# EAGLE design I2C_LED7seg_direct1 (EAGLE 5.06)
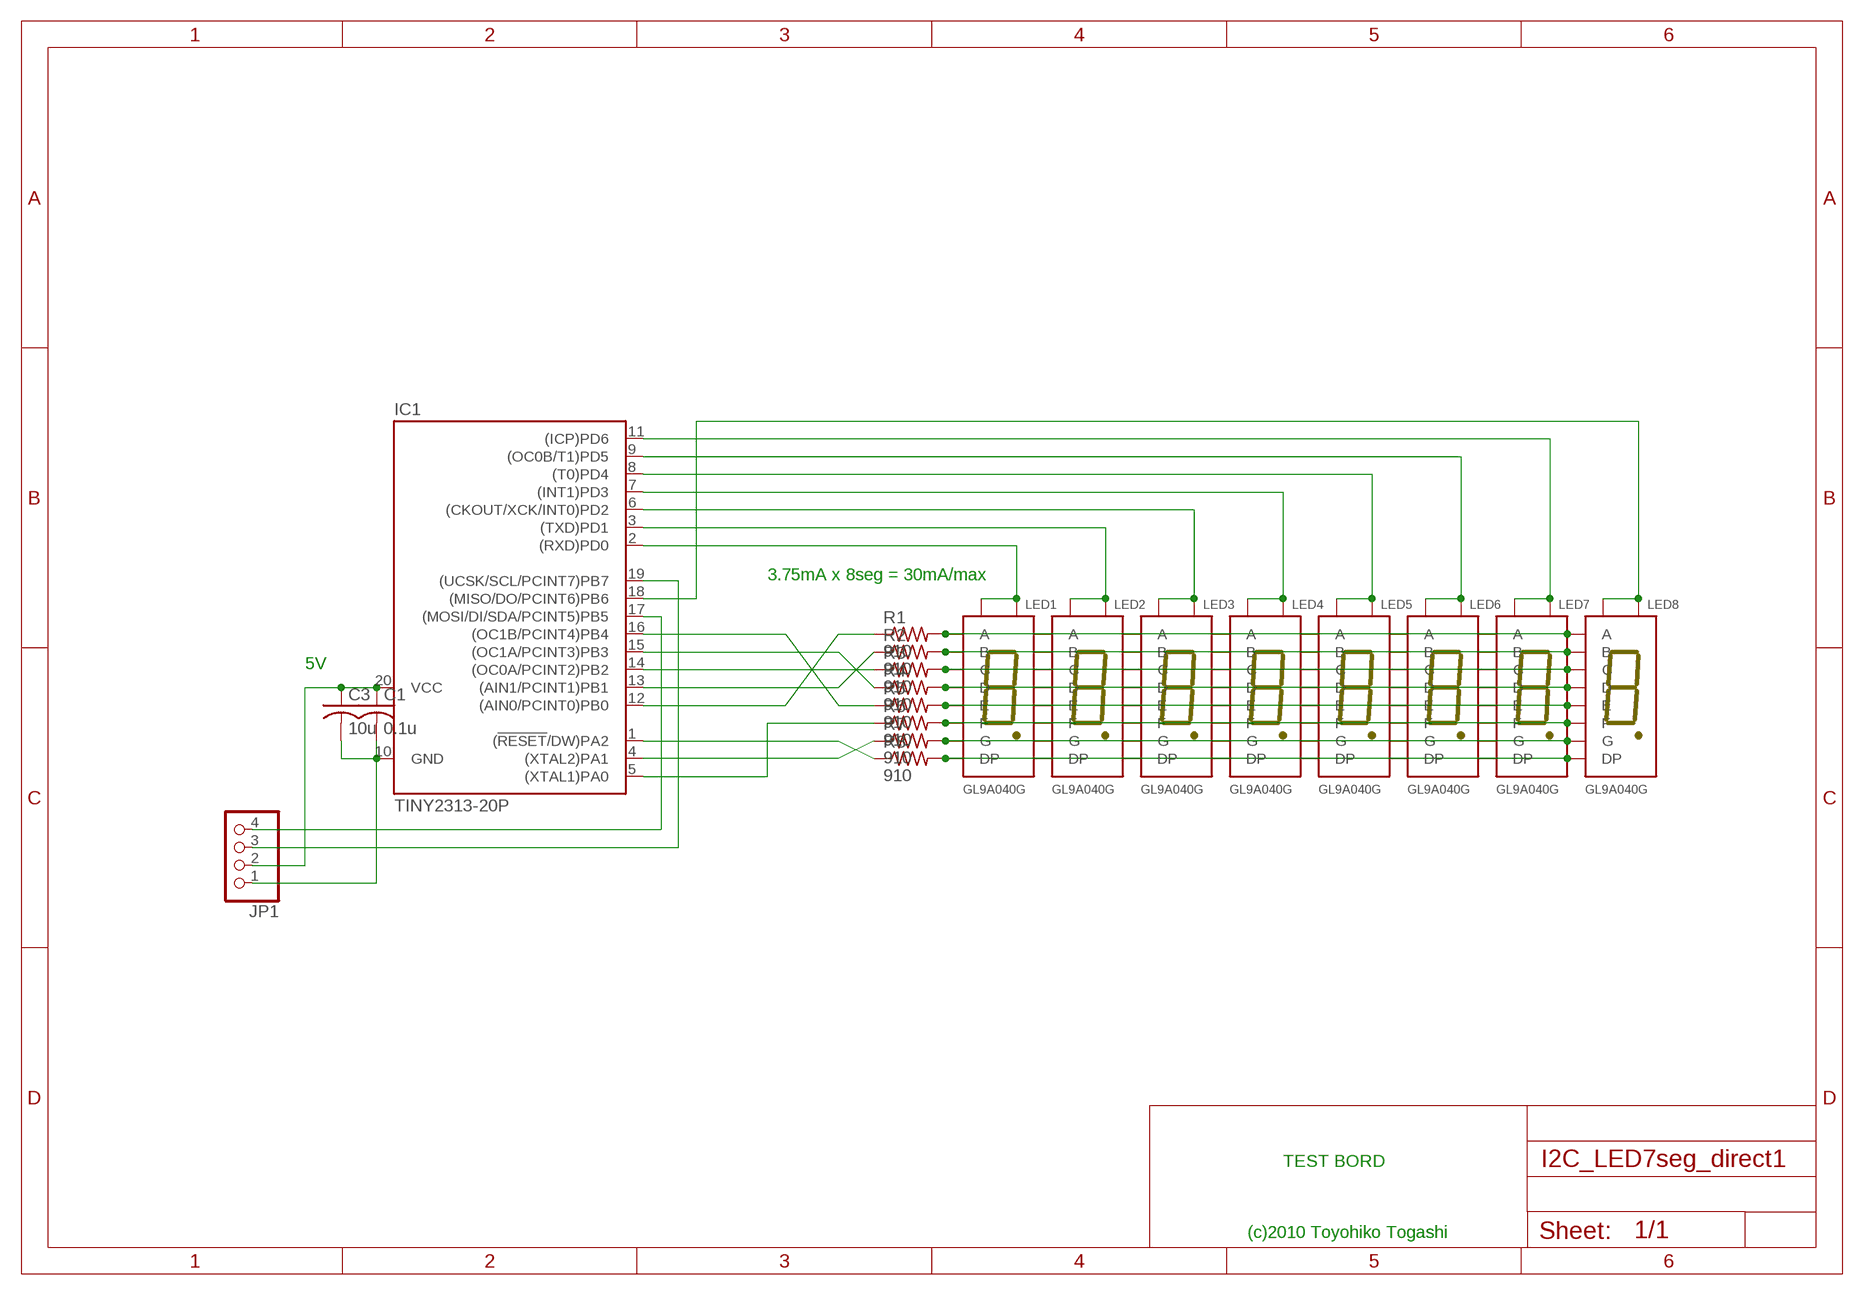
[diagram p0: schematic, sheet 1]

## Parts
C1  0.1u  C-US025-025X050  [C025-025X050]
C3  10u  C-US025-025X050  [C025-025X050]
IC1  TINY2313-20P  [DIL20]
JP1  PINHD-1X4  [1X04]
LED1  GL9A040G  [GL9A040G]
LED2  GL9A040G  [GL9A040G]
LED3  GL9A040G  [GL9A040G]
LED4  GL9A040G  [GL9A040G]
LED5  GL9A040G  [GL9A040G]
LED6  GL9A040G  [GL9A040G]
LED7  GL9A040G  [GL9A040G]
LED8  GL9A040G  [GL9A040G]
R1  910  R-US_0204/5  [0204/5]
R2  910  R-US_0204/5  [0204/5]
R3  910  R-US_0204/5  [0204/5]
R4  910  R-US_0204/5  [0204/5]
R5  910  R-US_0204/5  [0204/5]
R6  910  R-US_0204/5  [0204/5]
R7  910  R-US_0204/5  [0204/5]
R8  910  R-US_0204/5  [0204/5]

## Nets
N$1: C1.1 C3.1 IC1.20(VCC) JP1.2
N$2: LED1.P$10(A) LED2.P$10(A) LED3.P$10(A) LED4.P$10(A) LED5.P$10(A) LED6.P$10(A) LED7.P$10(A) LED8.P$10(A) R1.2
N$3: IC1.19((UCSK/SCL/PCINT7)PB7) JP1.3
N$4: IC1.17((MOSI/DI/SDA/PCINT5)PB5) JP1.4
N$6: LED1.P$9(B) LED2.P$9(B) LED3.P$9(B) LED4.P$9(B) LED5.P$9(B) LED6.P$9(B) LED7.P$9(B) LED8.P$9(B) R2.2
N$7: LED1.P$8(C) LED2.P$8(C) LED3.P$8(C) LED4.P$8(C) LED5.P$8(C) LED6.P$8(C) LED7.P$8(C) LED8.P$8(C) R3.2
N$8: LED1.P$5(D) LED2.P$5(D) LED3.P$5(D) LED4.P$5(D) LED5.P$5(D) LED6.P$5(D) LED7.P$5(D) LED8.P$5(D) R4.2
N$9: LED1.P$4(E) LED2.P$4(E) LED3.P$4(E) LED4.P$4(E) LED5.P$4(E) LED6.P$4(E) LED7.P$4(E) LED8.P$4(E) R5.2
N$10: LED1.P$2(F) LED2.P$2(F) LED3.P$2(F) LED4.P$2(F) LED5.P$2(F) LED6.P$2(F) LED7.P$2(F) LED8.P$2(F) R6.2
N$11: LED1.P$7(DP) LED2.P$7(DP) LED3.P$7(DP) LED4.P$7(DP) LED5.P$7(DP) LED6.P$7(DP) LED7.P$7(DP) LED8.P$7(DP) R8.2
N$12: LED1.P$3(G) LED2.P$3(G) LED3.P$3(G) LED4.P$3(G) LED5.P$3(G) LED6.P$3(G) LED7.P$3(G) LED8.P$3(G) R7.2
N$14: IC1.5((XTAL1)PA0) R6.1
N$15: IC1.4((XTAL2)PA1) R7.1
N$16: IC1.1((!RESET!/DW)PA2) R8.1
N$17: IC1.12((AIN0/PCINT0)PB0) R1.1
N$19: IC1.13((AIN1/PCINT1)PB1) R2.1
N$20: IC1.14((OC0A/PCINT2)PB2) R3.1
N$21: IC1.15((OC1A/PCINT3)PB3) R4.1
N$22: IC1.16((OC1B/PCINT4)PB4) R5.1
N$25: IC1.2((RXD)PD0) LED1.P$1(CA1) LED1.P$6(CA6)
N$28: IC1.18((MISO/DO/PCINT6)PB6) LED8.P$1(CA1) LED8.P$6(CA6)
N$33: C1.2 C3.2 IC1.10(GND) JP1.1
N$98: IC1.3((TXD)PD1) LED2.P$1(CA1) LED2.P$6(CA6)
N$99: IC1.6((CKOUT/XCK/INT0)PD2) LED3.P$1(CA1) LED3.P$6(CA6)
N$100: IC1.7((INT1)PD3) LED4.P$1(CA1) LED4.P$6(CA6)
N$101: IC1.8((T0)PD4) LED5.P$1(CA1) LED5.P$6(CA6)
N$102: IC1.9((OC0B/T1)PD5) LED6.P$1(CA1) LED6.P$6(CA6)
N$103: IC1.11((ICP)PD6) LED7.P$1(CA1) LED7.P$6(CA6)

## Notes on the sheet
- 3.75mA x 8seg = 30mA/max
- 5V
- TEST BORD
- (c)2010 Toyohiko Togashi

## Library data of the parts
C1 C3 = rcl:C-US: CAPACITOR, American symbol
IC1 = TOG:TINY2313: 8-bit AVR Microcontroller with 2K Bytes Flash Source: http://www.atmel.com .. doc2543.pdf
JP1 = pinhead:PINHD-1X4: PIN HEADER
LED1-LED8 = TOG:GL9A040G: 7 Segment LED
R1-R8 = rcl:R-US_: RESISTOR, American symbol

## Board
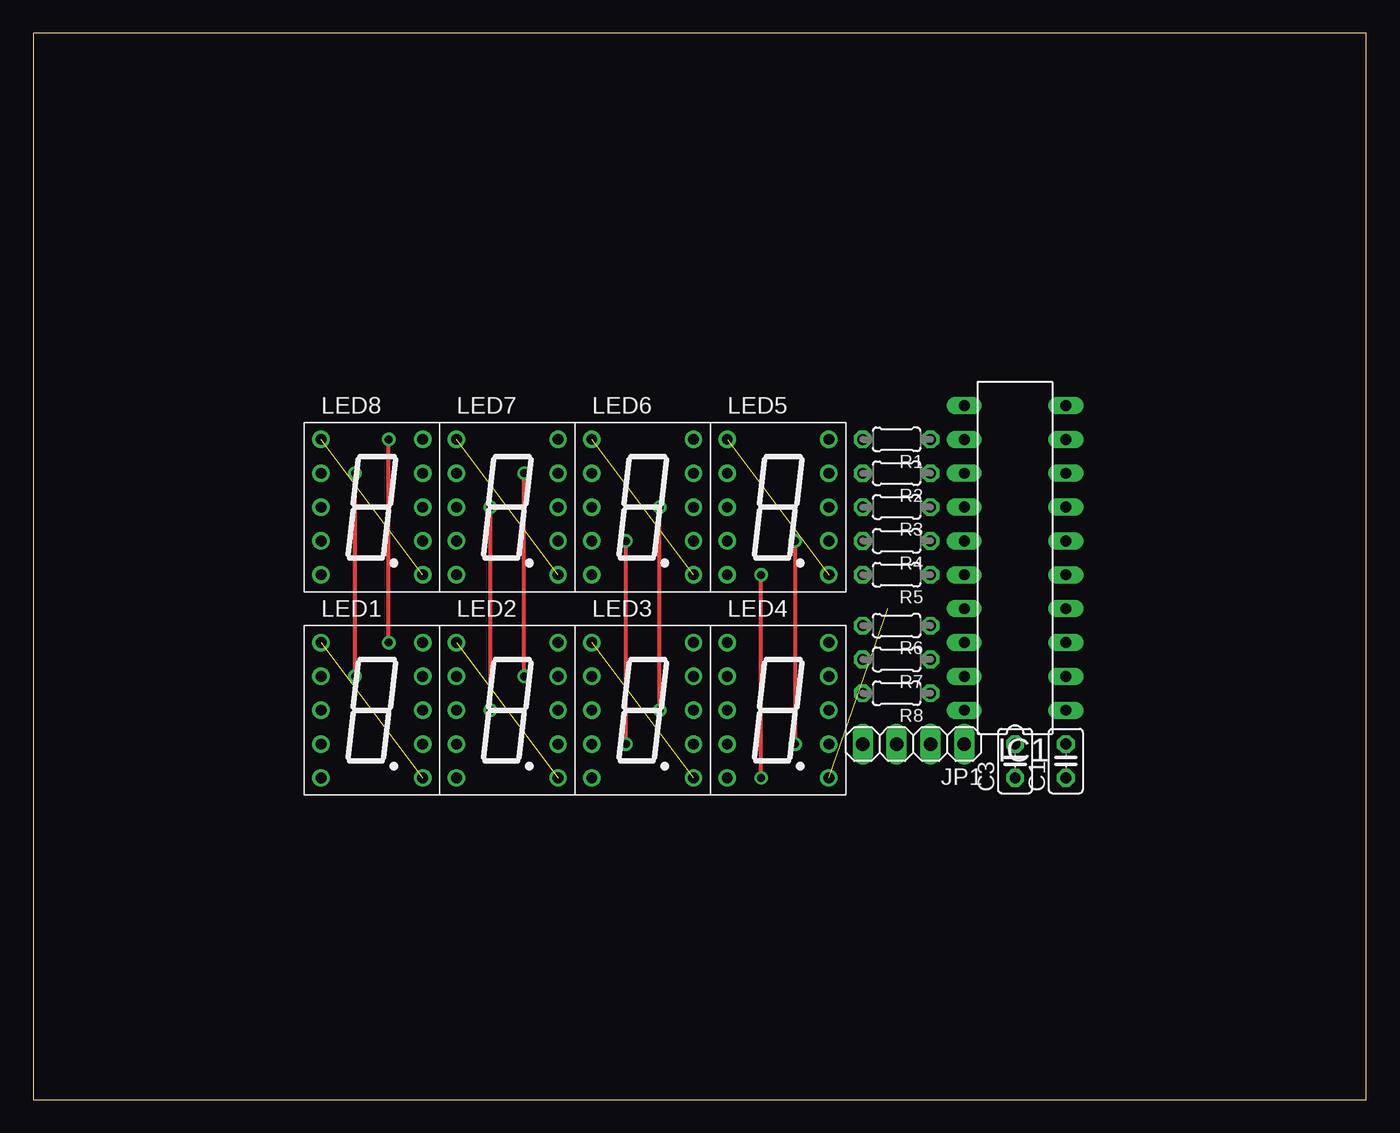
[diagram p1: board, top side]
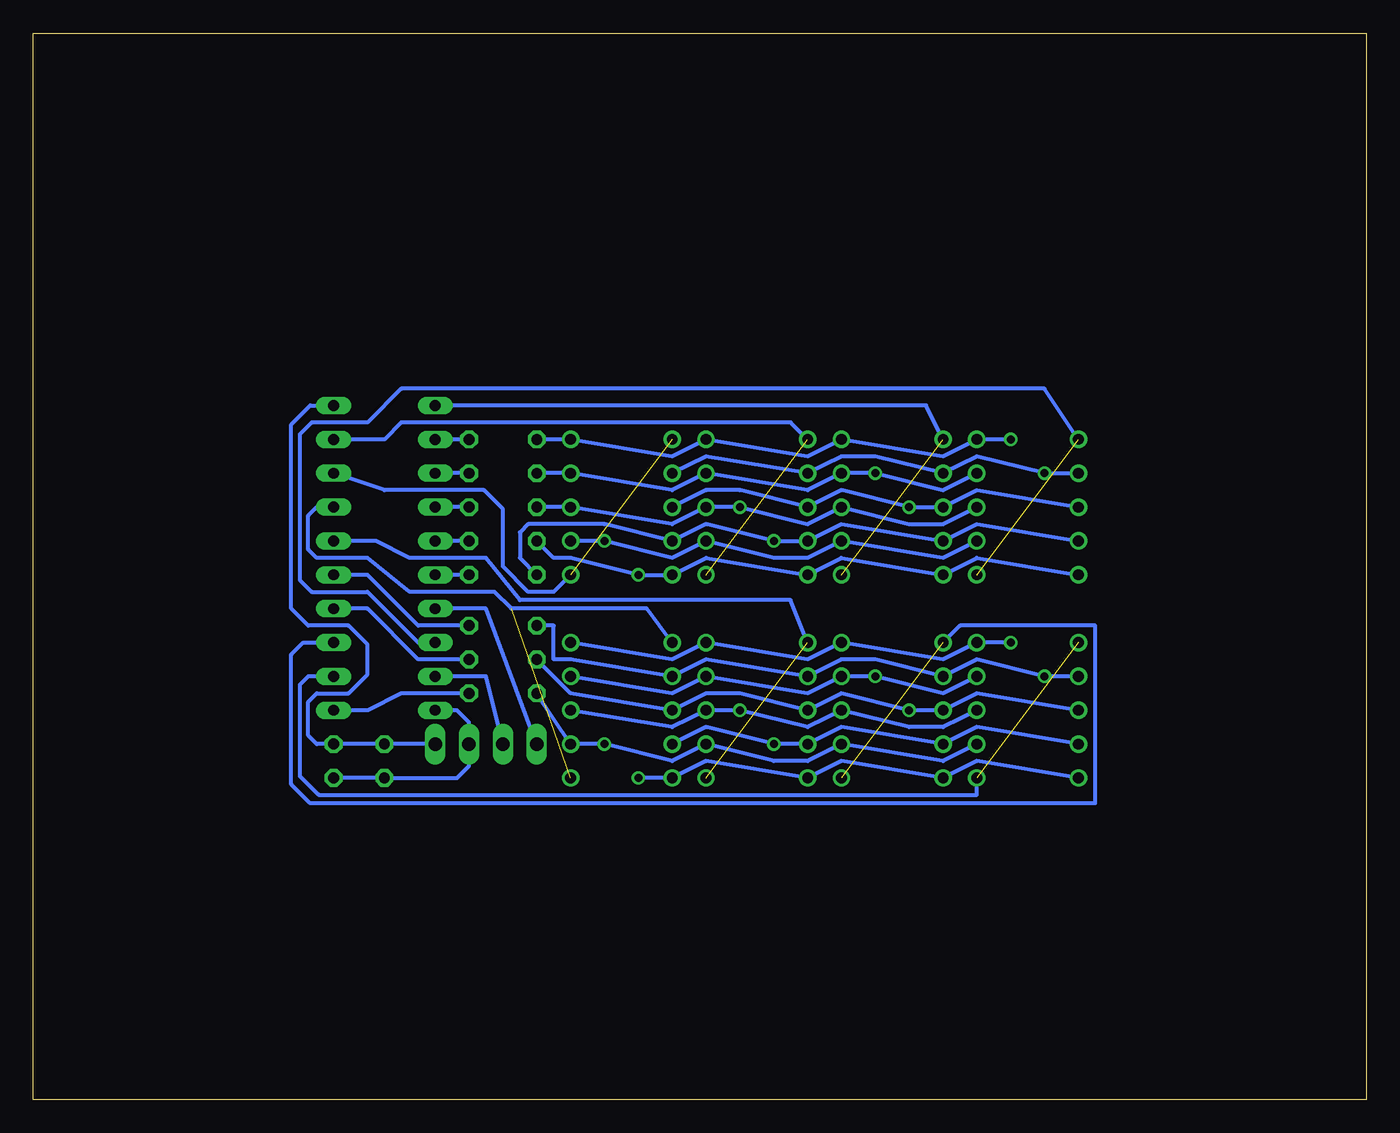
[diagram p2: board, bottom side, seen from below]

Size 100 x 80 mm. Coordinates in mm from the lower left corner, seen from the top.
Outline: 0,0 100,0 100,80 0,80 0,0
Copper layers (1*16): Top 0.035mm / dielectric 1.5mm / Bottom 0.035mm
Design rules "default": minimum track width 10mil, minimum drill 24mil, track to track 8mil, track to pad 8mil, pad to pad 8mil, via to via 8mil, smd to smd 8mil, copper to edge 40mil, drill to drill 8mil, minimum pad ring 10mil, minimum via ring 8mil, stop-mask expansion 4mil, vias tented up to drill 0mil, thermal gap 10mil

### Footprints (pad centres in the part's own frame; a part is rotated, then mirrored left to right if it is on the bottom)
C025-025X050 = drill 0.813 octagon: 1 -1.27,0; 2 1.27,0
DIL20 = drill 0.813 long: 1 -11.43,-3.81; 2 -8.89,-3.81; 3 -6.35,-3.81; 4 -3.81,-3.81; 5 -1.27,-3.81; 6 1.27,-3.81; 7 3.81,-3.81; 8 6.35,-3.81; 9 8.89,-3.81; 10 11.43,-3.81; 11 11.43,3.81; 12 8.89,3.81; 13 6.35,3.81; 14 3.81,3.81; 15 1.27,3.81; 16 -1.27,3.81; 17 -3.81,3.81; 18 -6.35,3.81; 19 -8.89,3.81; 20 -11.43,3.81
1X04 = drill 1.016 long: 1 -3.81,0; 2 -1.27,0; 3 1.27,0; 4 3.81,0
GL9A040G = drill 0.8 round: P$1 -3.81,5.08; P$2 -3.81,2.54; P$3 -3.81,0; P$4 -3.81,-2.54; P$5 -3.81,-5.08; P$6 3.81,-5.08; P$7 3.81,-2.54; P$8 3.81,0; P$9 3.81,2.54; P$10 3.81,5.08
0204/5 = drill 0.813 octagon: 1 -2.54,0; 2 2.54,0

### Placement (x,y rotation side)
C1  77.47,25.4 90 top
C3  73.66,25.4 90 top
IC1  73.66,40.64 90 top
JP1  66.04,26.67 180 top
LED1  25.4,29.21 0 top
LED2  35.56,29.21 0 top
LED3  45.72,29.21 0 top
LED4  55.88,29.21 0 top
LED5  55.88,44.45 0 top
LED6  45.72,44.45 0 top
LED7  35.56,44.45 0 top
LED8  25.4,44.45 0 top
R1  64.77,49.53 180 top
R2  64.77,46.99 180 top
R3  64.77,44.45 180 top
R4  64.77,41.91 180 top
R5  64.77,39.37 180 top
R6  64.77,35.56 180 top
R7  64.77,33.02 180 top
R8  64.77,30.48 180 top

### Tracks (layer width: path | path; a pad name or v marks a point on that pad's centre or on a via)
N$1
  Bottom 0.305: IC1.20 68.21,29.21 67.31,28.31 JP1.2 67.31,25.03 68.21,24.13 C3.1 C1.1
N$2  (via drill 0.6)
  Top 0.305: v26.67,34.29 v26.67,49.53
  Bottom 0.305: v26.67,49.53 LED8.P$10 31.75,48.26 LED7.P$10 41.91,48.26 LED6.P$10 52.07,48.26 LED5.P$10 R1.2 | v26.67,34.29 LED1.P$10 31.75,33.02 LED2.P$10 41.91,33.02 LED3.P$10 52.07,33.02 LED4.P$10
N$3
  Bottom 0.305: JP1.3 66.04,31.75 IC1.19
N$4
  Bottom 0.305: JP1.4 66.04,36.83 IC1.17
N$6  (via drill 0.6)
  Top 0.305: v36.83,31.75 v36.83,46.99
  Bottom 0.305: LED8.P$9 31.75,45.72 v36.83,46.99 LED7.P$9 41.91,45.72 LED6.P$9 52.07,45.72 LED5.P$9 R2.2 | LED1.P$9 31.75,30.48 v36.83,31.75 LED2.P$9 41.91,30.48 LED3.P$9 52.07,30.48 LED4.P$9
N$7  (via drill 0.6)
  Top 0.305: v46.99,29.21 v46.99,44.45
  Bottom 0.305: LED8.P$8 31.75,43.18 34.29,43.18 LED7.P$8 41.91,43.18 v46.99,44.45 LED6.P$8 52.07,43.18 LED5.P$8 R3.2 | LED1.P$8 31.75,27.94 34.29,27.94 LED2.P$8 41.91,27.94 v46.99,29.21 LED3.P$8 52.07,27.94 LED4.P$8
N$8  (via drill 0.6)
  Top 0.305: v54.61,24.13 v54.61,39.37
  Bottom 0.305: v54.61,24.13 LED4.P$5 49.53,25.4 LED3.P$5 39.37,25.4 LED2.P$5 29.21,25.4 LED1.P$5 | LED8.P$5 29.21,40.64 LED7.P$5 39.37,40.64 LED6.P$5 49.53,40.64 LED5.P$5 v54.61,39.37 59.69,40.64 60.96,40.64 R4.2
N$9  (via drill 0.6)
  Top 0.305: v44.45,26.67 v44.45,41.91
  Bottom 0.305: LED8.P$4 29.21,43.18 LED7.P$4 39.37,43.18 LED6.P$4 v44.45,41.91 49.53,43.18 LED5.P$4 57.15,43.18 62.87,43.18 63.5,42.55 63.5,40.64 R5.2 | LED1.P$4 29.21,27.94 LED2.P$4 39.37,27.94 LED3.P$4 v44.45,26.67 49.53,27.94 LED4.P$4
N$10  (via drill 0.6)
  Top 0.305: v24.13,31.75 v24.13,46.99
  Bottom 0.305: LED8.P$2 v24.13,46.99 29.21,48.26 LED7.P$2 36.83,48.26 39.37,48.26 LED6.P$2 49.53,48.26 LED5.P$2 | LED1.P$2 v24.13,31.75 29.21,33.02 LED2.P$2 36.83,33.02 39.37,33.02 LED3.P$2 49.53,33.02 LED4.P$2 59.69,33.02 60.96,33.02 60.96,35.56 R6.2
N$11  (via drill 0.6)
  Top 0.305: v57.15,41.91 v57.15,26.67
  Bottom 0.305: LED5.P$7 v57.15,41.91 52.07,40.64 LED6.P$7 44.45,40.64 41.91,40.64 LED7.P$7 31.75,40.64 LED8.P$7 | LED1.P$7 31.75,25.4 LED2.P$7 41.91,25.4 44.45,25.4 LED3.P$7 52.07,25.4 v57.15,26.67 LED4.P$7 R8.2
N$12  (via drill 0.6)
  Top 0.305: v34.29,29.21 v34.29,44.45
  Bottom 0.305: LED8.P$3 29.21,45.72 LED7.P$3 v34.29,44.45 39.37,45.72 LED6.P$3 46.99,45.72 49.53,45.72 LED5.P$3 | LED1.P$3 29.21,30.48 LED2.P$3 v34.29,29.21 39.37,30.48 LED3.P$3 46.99,30.48 49.53,30.48 LED4.P$3 59.69,30.48 R7.2
N$14
  Bottom 0.305: R6.1 71.12,35.56 74.93,39.37 IC1.5
N$15
  Bottom 0.305: R7.1 71.12,33.02 74.93,36.83 IC1.4
N$16
  Bottom 0.305: R8.1 72.39,30.48 74.93,29.21 IC1.1
N$17
  Bottom 0.305: R1.1 IC1.12
N$19
  Bottom 0.305: R2.1 IC1.13
N$20
  Bottom 0.305: R3.1 IC1.14
N$21
  Bottom 0.305: R4.1 IC1.15
N$22
  Bottom 0.305: R5.1 IC1.16
N$25  (1 unrouted)
  Bottom 0.305: IC1.2 79.38,31.75 80.01,31.11 80.01,24.28 78.59,22.86 29.21,22.86 LED1.P$6
N$28  (1 unrouted)
  Bottom 0.305: IC1.18 71.12,34.29 74.93,38.1 79.11,38.1 80.01,39 80.01,49.9 79.11,50.8 74.93,50.8 72.39,53.34 24.13,53.34 LED8.P$1
N$33
  Bottom 0.305: JP1.1 C3.2 C1.2 78.74,26.67 79.38,27.3 79.38,29.84 78.74,30.48 76.35,30.48 74.93,31.9 74.93,34.14 76.35,35.56 79.38,35.56 80.64,36.83 80.64,50.65 79.22,52.07 IC1.10
N$98  (1 unrouted)
  Bottom 0.305: IC1.3 79.75,34.29 80.64,33.39 80.64,23.64 79.22,22.23 20.32,22.23 20.32,35.56 30.48,35.56 LED2.P$1
N$99  (1 unrouted)
  Bottom 0.305: IC1.6 74.3,41.91 71.75,40.64 66.04,40.64 63.5,37.47 43.18,37.47 LED3.P$1
N$100  (1 unrouted)
  Bottom 0.305: IC1.7 78.74,44.45 79.38,43.81 79.38,41.27 78.74,40.64 74.93,40.64 71.75,38.1 65.41,38.1 64.14,36.83 53.98,36.83 LED4.P$1
N$101  (1 unrouted)
  Bottom 0.305: LED5.P$6 60.96,38.1 62.87,38.1 64.77,40.01 64.77,44.3 66.19,45.72 73.66,45.72 IC1.8
N$102  (1 unrouted)
  Bottom 0.305: IC1.9 73.66,49.53 72.39,50.8 43.18,50.8 LED6.P$1
N$103  (1 unrouted)
  Bottom 0.305: IC1.11 33.02,52.07 LED7.P$1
